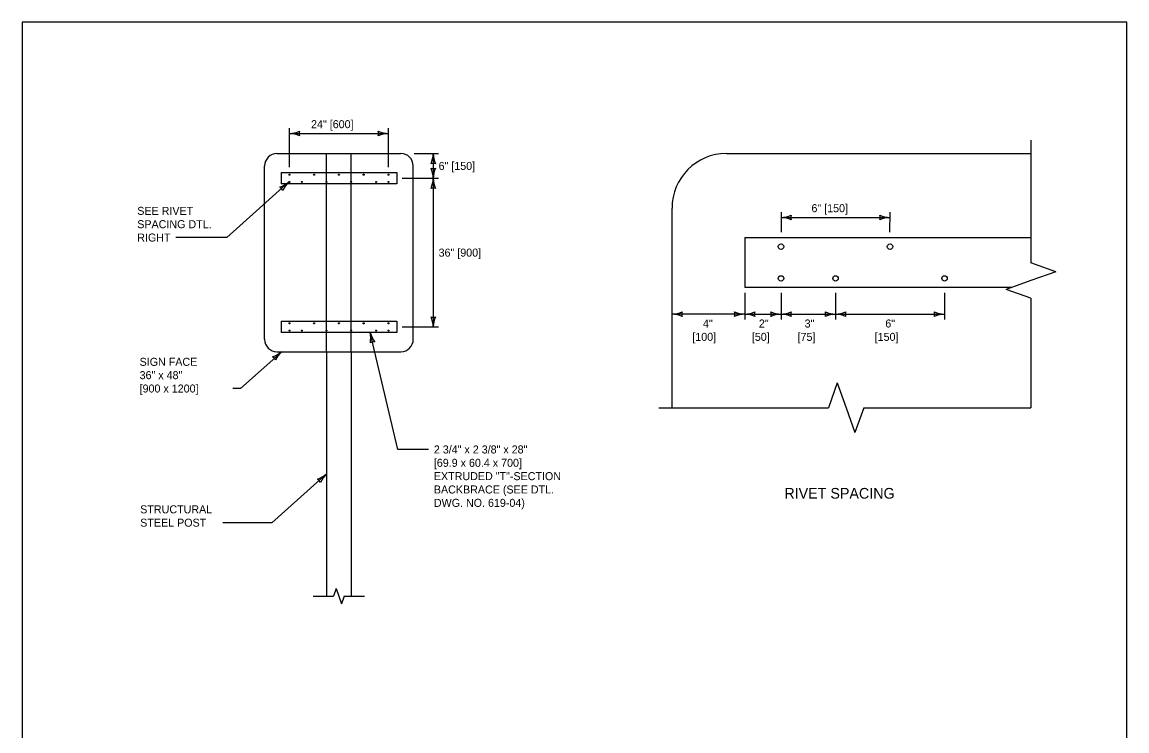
# Model space of a CAD drawing. Extents: x 49991.4 to 50021, y 49987.6 to 50011.4.
# Drawn here: x 50000.34 to 50008.61, y 50005.95 to 50011.26 of the extents above; entities that cross this region are included whole.
import ezdxf

# ---------------------------------------------------------------- set-up
doc = ezdxf.new("R2010")
doc.units = 0
for name, color, linetype in [('Level 1', 7, 'Continuous'), ('Level 2', 7, 'Continuous'), ('Level 3', 7, 'Continuous'), ('Level 4', 7, 'Continuous'), ('Level 6', 7, 'Continuous')]:
    doc.layers.add(name, color=color, linetype=linetype)

msp = doc.modelspace()

# ---------------------------------------------------------------- linework, layer by layer
at = {"layer": 'Level 1'}
for p, q in [((50002.2456, 50010.2778), (50003.1738, 50010.2778)), ((50005.6143, 50010.2778), (50007.8953, 50010.2778)), ((50002.1529, 50008.8858), (50002.1529, 50010.185)), ((50003.2667, 50008.8858), (50003.2667, 50010.185)), ((50005.206, 50008.3728), (50005.206, 50009.8695)), ((50002.2456, 50008.7928), (50003.1738, 50008.7928)), ((50002.6169, 50008.7928), (50002.6169, 50006.9608)), ((50002.8026, 50008.7928), (50002.8026, 50006.9608))]:
    msp.add_line(p, q, dxfattribs=at)
msp.add_lwpolyline([(50008.6146, 50011.2628), (50000.3356, 50011.2628), (50000.3356, 50000.0624), (50008.6146, 50000.0624)], close=True, dxfattribs=at)
for centre, radius in [((50002.3385, 50010.1193), 0.00387), ((50002.3385, 50010.0652), 0.00387), ((50002.4313, 50010.0652), 0.00387), ((50002.5241, 50010.1193), 0.00387), ((50002.6169, 50010.0652), 0.00387), ((50002.7097, 50010.1193), 0.00387), ((50002.8025, 50010.0652), 0.00387), ((50002.8953, 50010.1193), 0.00387), ((50002.9881, 50010.0652), 0.00387), ((50003.081, 50010.1193), 0.00387), ((50003.081, 50010.0652), 0.00387), ((50006.0227, 50009.5803), 0.0204), ((50006.8394, 50009.5803), 0.0204), ((50006.0227, 50009.3421), 0.0204), ((50006.431, 50009.3421), 0.0204), ((50007.2478, 50009.3421), 0.0204), ((50002.3385, 50009.0056), 0.00387), ((50002.5241, 50009.0056), 0.00387), ((50002.7097, 50009.0056), 0.00387), ((50002.8953, 50009.0056), 0.00387), ((50003.081, 50009.0056), 0.00387), ((50002.3385, 50008.9515), 0.00387), ((50002.4313, 50008.9515), 0.00387), ((50002.6169, 50008.9515), 0.00387), ((50002.8025, 50008.9515), 0.00387), ((50002.9881, 50008.9515), 0.00387), ((50003.081, 50008.9515), 0.00387)]:
    msp.add_circle(centre, radius, dxfattribs=at)
for centre, radius, start, end in [((50002.2457, 50010.185), 0.0928, 90.03018, 180.03018), ((50003.1738, 50010.185), 0.0929, 0.03085, 90.03085), ((50005.6143, 50009.8695), 0.4083, 90, 180), ((50002.2457, 50008.8857), 0.0929, 179.90744, 269.90744), ((50003.1738, 50008.8857), 0.093, 270.03082, 0.03082)]:
    msp.add_arc(centre, radius, start, end, dxfattribs=at)
at = {"layer": 'Level 3'}
for p, q in [((50002.3385, 50010.1747), (50002.3385, 50010.4678)), ((50003.081, 50010.1747), (50003.081, 50010.4678)), ((50002.3385, 50010.4278), (50003.081, 50010.4278)), ((50003.2738, 50010.2778), (50003.4567, 50010.2778)), ((50003.4167, 50010.2778), (50003.4167, 50010.0922)), ((50002.3346, 50010.0652), (50001.8688, 50009.6484)), ((50003.1829, 50010.0922), (50003.4567, 50010.0922)), ((50003.4167, 50010.0922), (50003.4167, 50008.9786)), ((50006.0227, 50009.8383), (50006.0227, 50009.6883)), ((50006.0227, 50009.7983), (50006.8394, 50009.7983)), ((50006.8393, 50009.6883), (50006.8394, 50009.8383)), ((50001.8688, 50009.6484), (50001.4877, 50009.6484)), ((50005.7505, 50009.2341), (50005.7505, 50009.0341)), ((50006.0227, 50009.2341), (50006.0227, 50009.0341)), ((50006.431, 50009.2341), (50006.431, 50009.0341)), ((50007.2478, 50009.2341), (50007.2478, 50009.0341)), ((50005.7505, 50009.0741), (50005.206, 50009.0741)), ((50005.7505, 50009.0741), (50006.0227, 50009.0741)), ((50006.0227, 50009.0741), (50006.431, 50009.0741)), ((50006.431, 50009.0741), (50007.2478, 50009.0741)), ((50003.1829, 50008.9786), (50003.4567, 50008.9786)), ((50003.1511, 50008.0603), (50002.9442, 50008.9361)), ((50002.2809, 50008.7928), (50001.9713, 50008.5169)), ((50001.9713, 50008.5169), (50001.9148, 50008.517)), ((50003.3812, 50008.0603), (50003.1511, 50008.0603)), ((50002.6169, 50007.8768), (50002.2069, 50007.5116)), ((50002.2069, 50007.5116), (50001.8398, 50007.5116))]:
    msp.add_line(p, q, dxfattribs=at)
for centre, radius, start, end in [((50002.327, 50010.6605), 0.233, 272.82731, 292.07716), ((50002.3293, 50010.2057), 0.2223, 67.45601, 87.63952), ((50002.4667, 50010.4278), 0.0548, 162.13882, 197.86118), ((50003.0902, 50010.6499), 0.2223, 247.45601, 267.63952), ((50002.9528, 50010.4278), 0.0548, 342.13882, 17.86118), ((50003.0925, 50010.1951), 0.233, 92.82731, 112.07716), ((50003.1946, 50010.287), 0.2223, 337.45601, 357.63952), ((50003.6494, 50010.2893), 0.233, 182.82731, 202.07716), ((50003.4167, 50010.1496), 0.0548, 72.13882, 107.86118), ((50003.4167, 50010.2204), 0.0548, 252.13882, 287.86118), ((50003.184, 50010.0807), 0.233, 2.82731, 22.07716), ((50003.6388, 50010.083), 0.2223, 157.45601, 177.63952), ((50002.1933, 50010.2368), 0.2223, 289.27949, 309.463), ((50002.4983, 50009.8995), 0.233, 134.65079, 153.90064), ((50003.1946, 50010.1014), 0.2223, 337.45601, 357.63952), ((50003.6494, 50010.1037), 0.233, 182.82731, 202.07716), ((50002.239, 50009.9797), 0.0548, 23.9623, 59.68466), ((50003.4167, 50009.964), 0.0548, 72.13882, 107.86118), ((50006.0112, 50010.031), 0.233, 272.82731, 292.07716), ((50006.0135, 50009.5762), 0.2223, 67.45601, 87.63952), ((50006.1509, 50009.7983), 0.0548, 162.13882, 197.86118), ((50006.8485, 50010.0204), 0.2223, 247.45601, 267.63952), ((50006.7112, 50009.7983), 0.0548, 342.13882, 17.86118), ((50006.8509, 50009.5656), 0.233, 92.82731, 112.07716), ((50003.4167, 50009.1068), 0.0548, 252.13882, 287.86118), ((50003.184, 50008.9671), 0.233, 2.82731, 22.07716), ((50003.6388, 50008.9694), 0.2223, 157.45601, 177.63952), ((50005.1945, 50009.3068), 0.233, 272.82731, 292.07716), ((50005.1968, 50008.852), 0.2223, 67.45601, 87.63952), ((50005.3342, 50009.0741), 0.0548, 162.13882, 197.86118), ((50005.7597, 50009.2962), 0.2223, 247.45601, 267.63952), ((50005.6223, 50009.0741), 0.0548, 342.13882, 17.86118), ((50005.762, 50008.8414), 0.233, 92.82731, 112.07716), ((50005.739, 50009.3068), 0.233, 272.82731, 292.07716), ((50005.7413, 50008.852), 0.2223, 67.45601, 87.63952), ((50005.8787, 50009.0741), 0.0548, 162.13882, 197.86118), ((50006.0319, 50009.2962), 0.2223, 247.45601, 267.63952), ((50005.8945, 50009.0741), 0.0548, 342.13882, 17.86118), ((50006.0342, 50008.8414), 0.233, 92.82731, 112.07716), ((50006.0112, 50009.3068), 0.233, 272.82731, 292.07716), ((50006.0135, 50008.852), 0.2223, 67.45601, 87.63952), ((50006.1509, 50009.0741), 0.0548, 162.13882, 197.86118), ((50006.4402, 50009.2962), 0.2223, 247.45601, 267.63952), ((50006.3028, 50009.0741), 0.0548, 342.13882, 17.86118), ((50006.4425, 50008.8414), 0.233, 92.82731, 112.07716), ((50006.4195, 50009.3068), 0.233, 272.82731, 292.07716), ((50006.4218, 50008.852), 0.2223, 67.45601, 87.63952), ((50006.5592, 50009.0741), 0.0548, 162.13882, 197.86118), ((50007.257, 50009.2962), 0.2223, 247.45601, 267.63952), ((50007.1196, 50009.0741), 0.0548, 342.13882, 17.86118), ((50007.2593, 50008.8414), 0.233, 92.82731, 112.07716), ((50002.7259, 50008.8939), 0.2223, 350.74793, 10.93144), ((50003.168, 50009.0008), 0.233, 196.11923, 215.36908), ((50002.9737, 50008.8113), 0.0548, 85.43074, 121.1531), ((50002.14, 50008.9648), 0.2223, 289.14848, 309.33199), ((50002.1852, 50008.7075), 0.0548, 23.83129, 59.55365), ((50002.4443, 50008.6267), 0.233, 134.51978, 153.76963), ((50002.476, 50008.0488), 0.2223, 289.14848, 309.33199), ((50002.5212, 50007.7915), 0.0548, 23.83129, 59.55365), ((50002.7803, 50007.7107), 0.233, 134.51978, 153.76963)]:
    msp.add_arc(centre, radius, start, end, dxfattribs=at)
at = {"layer": 'Level 4'}
for p, q in [((50002.6169, 50008.7928), (50002.6169, 50010.2778)), ((50002.8026, 50008.7928), (50002.8026, 50010.2778)), ((50002.2767, 50010.1347), (50002.2767, 50010.0498)), ((50002.2767, 50010.1347), (50003.1429, 50010.1347)), ((50003.1429, 50010.1347), (50003.1429, 50010.0498)), ((50003.1429, 50010.0498), (50002.2767, 50010.0498)), ((50005.7505, 50009.6483), (50005.7505, 50009.2741)), ((50005.7505, 50009.6483), (50007.8953, 50009.6483)), ((50007.7505, 50009.2741), (50005.7505, 50009.2741)), ((50002.2767, 50009.021), (50002.2767, 50008.9361)), ((50002.2767, 50009.021), (50003.1429, 50009.021)), ((50003.1429, 50009.021), (50003.1429, 50008.9361)), ((50003.1429, 50008.9361), (50002.2767, 50008.9361))]:
    msp.add_line(p, q, dxfattribs=at)
at = {"layer": 'Level 6'}
for p, q in [((50007.8953, 50010.3778), (50007.8953, 50009.4578)), ((50008.0817, 50009.3914), (50007.8953, 50009.4578)), ((50008.0817, 50009.3914), (50007.8953, 50009.3253)), ((50007.8953, 50009.3253), (50007.7086, 50009.2593)), ((50007.8953, 50009.1931), (50007.7086, 50009.2593)), ((50007.8953, 50009.1931), (50007.8953, 50008.3728)), ((50006.4438, 50008.5594), (50006.3776, 50008.3728)), ((50006.4438, 50008.5594), (50006.5098, 50008.3728)), ((50005.106, 50008.3728), (50006.3776, 50008.3728)), ((50006.5098, 50008.3728), (50006.576, 50008.1862)), ((50006.6422, 50008.3728), (50006.576, 50008.1862)), ((50006.6422, 50008.3728), (50007.8953, 50008.3728)), ((50002.6897, 50007.0174), (50002.6697, 50006.9608)), ((50002.6897, 50007.0174), (50002.7096, 50006.9608)), ((50002.5169, 50006.9608), (50002.6697, 50006.9608)), ((50002.7096, 50006.9608), (50002.7297, 50006.9043)), ((50002.7499, 50006.9608), (50002.7297, 50006.9043)), ((50002.7499, 50006.9608), (50002.9026, 50006.9608))]:
    msp.add_line(p, q, dxfattribs=at)

# ---------------------------------------------------------------- texts
at = {"layer": 'Level 2'}
for s, height, p in [('24" [600]', 0.06, (50002.501, 50010.4678)), ('6" [150]', 0.06, (50003.4567, 50010.155)), ('SEE RIVET ', 0.06, (50001.1985, 50009.8184)), ('6" [150]', 0.06, (50006.2507, 50009.8383)), ('SPACING DTL.', 0.06, (50001.1985, 50009.7184)), ('RIGHT', 0.06, (50001.1985, 50009.6184)), ('36" [900]', 0.06, (50003.4567, 50009.5054)), ('4"', 0.06, (50005.4379, 50008.9741)), ('2"', 0.06, (50005.8569, 50008.9741)), ('3"', 0.06, (50006.1996, 50008.9741)), ('6"', 0.06, (50006.8042, 50008.9741)), ('[100]', 0.06, (50005.358, 50008.8741)), ('[50]', 0.06, (50005.804, 50008.8741)), ('[75]', 0.06, (50006.1467, 50008.8741)), ('[150]', 0.06, (50006.7243, 50008.8741)), ('SIGN FACE', 0.06, (50001.2162, 50008.687)), ('36" x 48"', 0.06, (50001.2162, 50008.587)), ('[900 x 1200]', 0.06, (50001.2162, 50008.487)), ('2 3/4" x 2 3/8" x 28"', 0.06, (50003.4212, 50008.0303)), ('[69.9 x 60.4 x 700]', 0.06, (50003.4212, 50007.9303)), ('EXTRUDED "T"-SECTION', 0.06, (50003.4212, 50007.8303)), ('BACKBRACE (SEE DTL.', 0.06, (50003.4212, 50007.7303)), ('RIVET SPACING', 0.08, (50006.0478, 50007.6918)), ('DWG. NO. 619-04)', 0.06, (50003.4212, 50007.6303)), ('STRUCTURAL', 0.06, (50001.2206, 50007.5816)), ('STEEL POST', 0.06, (50001.2206, 50007.4816))]:
    msp.add_text(s, height=height, dxfattribs=at).set_placement(p)

doc.saveas('drawing.dxf')
